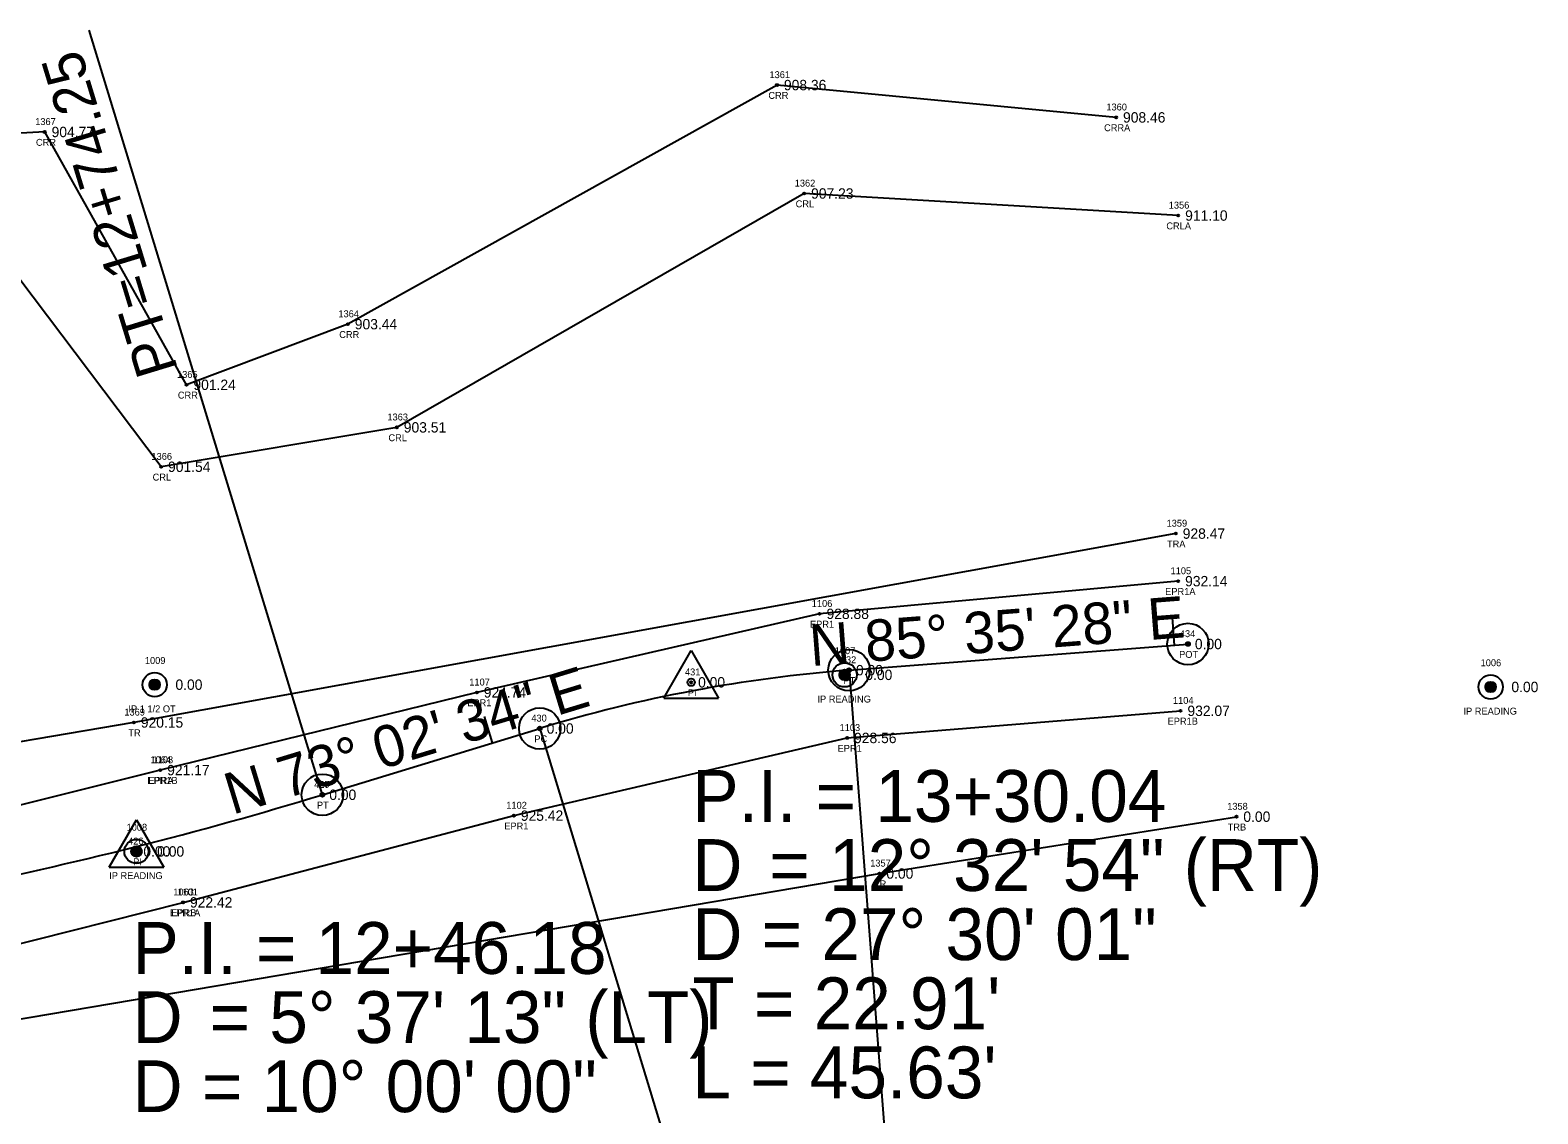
# Model space of a CAD drawing. Extents: x 1448136 to 1453623, y 1125056 to 1128842.
# Drawn here: x 1452130.2 to 1452348.3, y 1126988.8 to 1127145.6 of the extents above; entities that cross this region are included whole.
import ezdxf

# ---------------------------------------------------------------- set-up
doc = ezdxf.new("R2010")
doc.units = 0
for name, color, linetype in [('RD_EX_DV_Prop_txCode', 7, 'Continuous'), ('RD_EX_DV_PropPin', 7, 'Continuous'), ('RD_EX_H2O', 7, 'Continuous'), ('RD_EX_H2O_txCode', 7, 'Continuous'), ('RD_EX_Road', 7, 'Continuous'), ('RD_EX_Road_txCode', 7, 'Continuous'), ('RD_EX_TX_DV_Prop_ELEV', 7, 'Continuous'), ('RD_EX_TX_H2O_ELEV', 7, 'Continuous'), ('RD_EX_TX_Road_ELEV', 7, 'Continuous'), ('RD_EX_TX_VEG_ELEV', 7, 'Continuous'), ('RD_EX_VEG', 7, 'Continuous'), ('RD_EX_VEG_txCode', 7, 'Continuous'), ('RD_HC_Cl', 7, 'Continuous'), ('RD_HC_Data', 7, 'Continuous'), ('RD_HC_Data_Tic', 7, 'Continuous'), ('RD_HC_Survey_ELEV', 7, 'Continuous'), ('RD_HC_txCode', 7, 'Continuous'), ('RD_SMD_Locator', 7, 'Continuous')]:
    doc.layers.add(name, color=color, linetype=linetype)

msp = doc.modelspace()

# ---------------------------------------------------------------- linework, layer by layer
at = {"layer": 'RD_EX_DV_PropPin'}
for p, q in [((1452247.3, 1127052.08), (1452247.3, 1127052.47)), ((1452247.33, 1127051.98), (1452247.33, 1127052.57)), ((1452247.37, 1127051.91), (1452247.37, 1127052.64)), ((1452247.4, 1127051.85), (1452247.4, 1127052.7)), ((1452247.44, 1127051.8), (1452247.44, 1127052.75)), ((1452247.47, 1127051.76), (1452247.47, 1127052.79)), ((1452247.51, 1127051.72), (1452247.51, 1127052.83)), ((1452247.54, 1127051.69), (1452247.54, 1127052.86)), ((1452247.58, 1127051.66), (1452247.58, 1127052.88)), ((1452247.61, 1127051.64), (1452247.61, 1127052.91)), ((1452247.65, 1127051.62), (1452247.65, 1127052.93)), ((1452247.68, 1127051.6), (1452247.68, 1127052.95)), ((1452247.72, 1127051.58), (1452247.72, 1127052.97)), ((1452247.75, 1127051.57), (1452247.75, 1127052.98)), ((1452247.79, 1127051.55), (1452247.79, 1127053)), ((1452247.82, 1127051.54), (1452247.82, 1127053.01)), ((1452247.86, 1127051.53), (1452247.86, 1127053.02)), ((1452247.89, 1127051.53), (1452247.89, 1127053.02)), ((1452247.93, 1127051.52), (1452247.93, 1127053.03)), ((1452247.96, 1127051.52), (1452247.96, 1127053.03)), ((1452248, 1127051.51), (1452248, 1127053.03)), ((1452248.03, 1127051.51), (1452248.03, 1127053.04)), ((1452248.07, 1127051.51), (1452248.07, 1127053.03)), ((1452248.1, 1127051.52), (1452248.1, 1127053.03)), ((1452248.14, 1127051.52), (1452248.14, 1127053.03)), ((1452248.17, 1127051.53), (1452248.17, 1127053.02)), ((1452248.21, 1127051.53), (1452248.21, 1127053.02)), ((1452248.24, 1127051.54), (1452248.24, 1127053.01)), ((1452248.28, 1127051.55), (1452248.28, 1127053)), ((1452248.31, 1127051.57), (1452248.31, 1127052.98)), ((1452248.35, 1127051.58), (1452248.35, 1127052.97)), ((1452248.38, 1127051.6), (1452248.38, 1127052.95)), ((1452248.42, 1127051.62), (1452248.42, 1127052.93)), ((1452248.45, 1127051.64), (1452248.45, 1127052.91)), ((1452248.49, 1127051.66), (1452248.49, 1127052.88)), ((1452248.52, 1127051.69), (1452248.52, 1127052.86)), ((1452248.56, 1127051.72), (1452248.56, 1127052.83)), ((1452248.59, 1127051.76), (1452248.59, 1127052.79)), ((1452248.63, 1127051.8), (1452248.63, 1127052.75)), ((1452248.66, 1127051.85), (1452248.66, 1127052.7)), ((1452248.7, 1127051.91), (1452248.7, 1127052.64)), ((1452248.73, 1127051.98), (1452248.73, 1127052.57)), ((1452248.77, 1127052.08), (1452248.77, 1127052.47)), ((1452147.48, 1127050.65), (1452147.48, 1127051.04)), ((1452147.51, 1127050.55), (1452147.51, 1127051.14)), ((1452147.55, 1127050.48), (1452147.55, 1127051.21)), ((1452147.58, 1127050.42), (1452147.58, 1127051.27)), ((1452147.62, 1127050.37), (1452147.62, 1127051.32)), ((1452147.65, 1127050.33), (1452147.65, 1127051.36)), ((1452147.69, 1127050.29), (1452147.69, 1127051.4)), ((1452147.72, 1127050.26), (1452147.72, 1127051.43)), ((1452147.76, 1127050.24), (1452147.76, 1127051.46)), ((1452147.79, 1127050.21), (1452147.79, 1127051.48)), ((1452147.83, 1127050.19), (1452147.83, 1127051.5)), ((1452147.86, 1127050.17), (1452147.86, 1127051.52)), ((1452147.9, 1127050.15), (1452147.9, 1127051.54)), ((1452147.93, 1127050.14), (1452147.93, 1127051.55)), ((1452147.97, 1127050.12), (1452147.97, 1127051.57)), ((1452148, 1127050.11), (1452148, 1127051.58)), ((1452148.04, 1127050.1), (1452148.04, 1127051.59)), ((1452148.07, 1127050.1), (1452148.07, 1127051.59)), ((1452148.11, 1127050.09), (1452148.11, 1127051.6)), ((1452148.14, 1127050.09), (1452148.14, 1127051.6)), ((1452148.18, 1127050.09), (1452148.18, 1127051.61)), ((1452148.21, 1127050.08), (1452148.21, 1127051.61)), ((1452148.25, 1127050.09), (1452148.25, 1127051.61)), ((1452148.28, 1127050.09), (1452148.28, 1127051.6)), ((1452148.32, 1127050.09), (1452148.32, 1127051.6)), ((1452148.35, 1127050.1), (1452148.35, 1127051.59)), ((1452148.39, 1127050.1), (1452148.39, 1127051.59)), ((1452148.42, 1127050.11), (1452148.42, 1127051.58)), ((1452148.46, 1127050.12), (1452148.46, 1127051.57)), ((1452148.49, 1127050.14), (1452148.49, 1127051.55)), ((1452148.53, 1127050.15), (1452148.53, 1127051.54)), ((1452148.56, 1127050.17), (1452148.56, 1127051.52)), ((1452148.6, 1127050.19), (1452148.6, 1127051.5)), ((1452148.63, 1127050.21), (1452148.63, 1127051.48)), ((1452148.67, 1127050.24), (1452148.67, 1127051.46)), ((1452148.7, 1127050.26), (1452148.7, 1127051.43)), ((1452148.74, 1127050.29), (1452148.74, 1127051.4)), ((1452148.77, 1127050.33), (1452148.77, 1127051.36)), ((1452148.81, 1127050.37), (1452148.81, 1127051.32)), ((1452148.84, 1127050.42), (1452148.84, 1127051.27)), ((1452148.88, 1127050.48), (1452148.88, 1127051.21)), ((1452148.91, 1127050.55), (1452148.91, 1127051.14)), ((1452148.95, 1127050.65), (1452148.95, 1127051.04)), ((1452340.77, 1127050.33), (1452340.77, 1127050.72)), ((1452340.8, 1127050.22), (1452340.8, 1127050.82)), ((1452340.84, 1127050.15), (1452340.84, 1127050.89)), ((1452340.87, 1127050.1), (1452340.87, 1127050.95)), ((1452340.91, 1127050.05), (1452340.91, 1127051)), ((1452340.94, 1127050.01), (1452340.94, 1127051.04)), ((1452340.98, 1127049.97), (1452340.98, 1127051.07)), ((1452341.01, 1127049.94), (1452341.01, 1127051.1)), ((1452341.05, 1127049.91), (1452341.05, 1127051.13)), ((1452341.08, 1127049.89), (1452341.08, 1127051.16)), ((1452341.12, 1127049.87), (1452341.12, 1127051.18)), ((1452341.15, 1127049.85), (1452341.15, 1127051.2)), ((1452341.19, 1127049.83), (1452341.19, 1127051.22)), ((1452341.22, 1127049.82), (1452341.22, 1127051.23)), ((1452341.26, 1127049.8), (1452341.26, 1127051.24)), ((1452341.29, 1127049.79), (1452341.29, 1127051.25)), ((1452341.33, 1127049.78), (1452341.33, 1127051.26)), ((1452341.36, 1127049.77), (1452341.36, 1127051.27)), ((1452341.4, 1127049.77), (1452341.4, 1127051.28)), ((1452341.43, 1127049.77), (1452341.43, 1127051.28)), ((1452341.47, 1127049.76), (1452341.47, 1127051.28)), ((1452341.5, 1127049.76), (1452341.5, 1127051.28)), ((1452341.54, 1127049.76), (1452341.54, 1127051.28)), ((1452341.57, 1127049.77), (1452341.57, 1127051.28)), ((1452341.61, 1127049.77), (1452341.61, 1127051.28)), ((1452341.64, 1127049.77), (1452341.64, 1127051.27)), ((1452341.68, 1127049.78), (1452341.68, 1127051.26)), ((1452341.71, 1127049.79), (1452341.71, 1127051.25)), ((1452341.75, 1127049.8), (1452341.75, 1127051.24)), ((1452341.78, 1127049.82), (1452341.78, 1127051.23)), ((1452341.82, 1127049.83), (1452341.82, 1127051.22)), ((1452341.85, 1127049.85), (1452341.85, 1127051.2)), ((1452341.89, 1127049.87), (1452341.89, 1127051.18)), ((1452341.92, 1127049.89), (1452341.92, 1127051.16)), ((1452341.96, 1127049.91), (1452341.96, 1127051.13)), ((1452341.99, 1127049.94), (1452341.99, 1127051.1)), ((1452342.03, 1127049.97), (1452342.03, 1127051.07)), ((1452342.06, 1127050.01), (1452342.06, 1127051.04)), ((1452342.1, 1127050.05), (1452342.1, 1127051)), ((1452342.13, 1127050.1), (1452342.13, 1127050.95)), ((1452342.17, 1127050.15), (1452342.17, 1127050.89)), ((1452342.2, 1127050.22), (1452342.2, 1127050.82)), ((1452342.24, 1127050.33), (1452342.24, 1127050.72)), ((1452144.83, 1127026.52), (1452144.83, 1127026.91)), ((1452144.87, 1127026.42), (1452144.87, 1127027.02)), ((1452144.9, 1127026.35), (1452144.9, 1127027.09)), ((1452144.94, 1127026.29), (1452144.94, 1127027.15)), ((1452144.97, 1127026.24), (1452144.97, 1127027.19)), ((1452145.01, 1127026.2), (1452145.01, 1127027.23)), ((1452145.04, 1127026.17), (1452145.04, 1127027.27)), ((1452145.08, 1127026.14), (1452145.08, 1127027.3)), ((1452145.11, 1127026.11), (1452145.11, 1127027.33)), ((1452145.15, 1127026.08), (1452145.15, 1127027.35)), ((1452145.18, 1127026.06), (1452145.18, 1127027.37)), ((1452145.22, 1127026.04), (1452145.22, 1127027.39)), ((1452145.25, 1127026.03), (1452145.25, 1127027.41)), ((1452145.29, 1127026.01), (1452145.29, 1127027.43)), ((1452145.32, 1127026), (1452145.32, 1127027.44)), ((1452145.36, 1127025.99), (1452145.36, 1127027.45)), ((1452145.39, 1127025.98), (1452145.39, 1127027.46)), ((1452145.43, 1127025.97), (1452145.43, 1127027.47)), ((1452145.46, 1127025.96), (1452145.46, 1127027.47)), ((1452145.5, 1127025.96), (1452145.5, 1127027.48)), ((1452145.53, 1127025.96), (1452145.53, 1127027.48)), ((1452145.57, 1127025.96), (1452145.57, 1127027.48)), ((1452145.6, 1127025.96), (1452145.6, 1127027.48)), ((1452145.64, 1127025.96), (1452145.64, 1127027.48)), ((1452145.67, 1127025.96), (1452145.67, 1127027.47)), ((1452145.71, 1127025.97), (1452145.71, 1127027.47)), ((1452145.74, 1127025.98), (1452145.74, 1127027.46)), ((1452145.78, 1127025.99), (1452145.78, 1127027.45)), ((1452145.81, 1127026), (1452145.81, 1127027.44)), ((1452145.85, 1127026.01), (1452145.85, 1127027.43)), ((1452145.88, 1127026.03), (1452145.88, 1127027.41)), ((1452145.92, 1127026.04), (1452145.92, 1127027.39)), ((1452145.95, 1127026.06), (1452145.95, 1127027.37)), ((1452145.99, 1127026.08), (1452145.99, 1127027.35)), ((1452146.02, 1127026.11), (1452146.02, 1127027.33)), ((1452146.06, 1127026.14), (1452146.06, 1127027.3)), ((1452146.09, 1127026.17), (1452146.09, 1127027.27)), ((1452146.13, 1127026.2), (1452146.13, 1127027.23)), ((1452146.16, 1127026.24), (1452146.16, 1127027.19)), ((1452146.2, 1127026.29), (1452146.2, 1127027.15)), ((1452146.23, 1127026.35), (1452146.23, 1127027.09)), ((1452146.27, 1127026.42), (1452146.27, 1127027.02)), ((1452146.3, 1127026.52), (1452146.3, 1127026.91))]:
    msp.add_line(p, q, dxfattribs=at)
for centre, radius in [((1452148.21, 1127050.85), 1.75), ((1452248.03, 1127052.27), 1.75), ((1452248.03, 1127052.27), 0.761), ((1452341.5, 1127050.52), 1.75), ((1452148.21, 1127050.85), 0.761), ((1452341.5, 1127050.52), 0.761), ((1452145.57, 1127026.72), 1.75), ((1452145.57, 1127026.72), 0.761)]:
    msp.add_circle(centre, radius, dxfattribs=at)
at = {"layer": 'RD_EX_H2O'}
for points in [[(1452287.31, 1127132.93), (1452238.25, 1127137.61), (1452176.16, 1127103.01), (1452152.81, 1127094.24), (1452132.29, 1127130.82), (1452091.98, 1127128.64)], [(1452296.3, 1127118.73), (1452242.18, 1127121.92), (1452183.25, 1127088.08), (1452149.14, 1127082.38), (1452122.3, 1127117.91), (1452087.28, 1127110.29)]]:
    msp.add_lwpolyline(points, dxfattribs=at)
at = {"layer": 'RD_EX_Road'}
for points in [[(1452296.29, 1127065.83), (1452244.41, 1127061.1), (1452194.82, 1127049.73), (1452149.01, 1127038.49)], [(1452152.31, 1127019.35), (1452200.18, 1127031.9), (1452248.4, 1127043.14), (1452296.63, 1127047.07)], [(1452149.01, 1127038.49), (1452106.48, 1127027.85), (1452082.46, 1127021.08), (1452045.59, 1127011.82), (1452002.97, 1126996.13), (1451959.33, 1126960.73), (1451946.24, 1126940.07), (1451939.81, 1126935.13), (1451933.14, 1126934.05), (1451919.64, 1126943.05), (1451878.71, 1126971.14)], [(1452328.31, 1126661.73), (1452287.09, 1126689.84), (1452246.03, 1126718.01), (1452205.32, 1126746.34), (1452164.06, 1126774.06), (1452123.37, 1126802.45), (1452082.65, 1126830.42), (1452041.69, 1126858.52), (1452001.17, 1126886.81), (1451960.88, 1126914.87), (1451958.61, 1126919.72), (1451960.49, 1126923.88), (1451963.74, 1126930.05), (1451974.47, 1126951.2), (1452008.52, 1126983.3), (1452048.25, 1126993.66), (1452104.12, 1127007.18), (1452152.31, 1127019.35)]]:
    msp.add_lwpolyline(points, dxfattribs=at)
at = {"layer": 'RD_EX_VEG'}
for points in [[(1452295.95, 1127072.71), (1452145.2, 1127045.38), (1452114.53, 1127040.15), (1452064.57, 1127077.19)], [(1452345.62, 1126685.22), (1452295.11, 1126702.27), (1452093.42, 1126839.73), (1451967.4, 1126923.31), (1452009.8, 1126977.57), (1452079.04, 1126994.05), (1452253.07, 1127023.53), (1452304.72, 1127031.75)]]:
    msp.add_lwpolyline(points, dxfattribs=at)
at = {"layer": 'RD_HC_Cl'}
for p, q in [((1452248.67, 1127052.95), (1452297.71, 1127056.73)), ((1452172.47, 1127034.92), (1452203.92, 1127044.51))]:
    msp.add_line(p, q, dxfattribs=at)
for centre, radius, start, end in [((1452264.68, 1126845.22), 208.35, 94.4089, 106.9571), ((1452005.37, 1127582.96), 572.95, 281.3368, 286.9571)]:
    msp.add_arc(centre, radius, start, end, dxfattribs=at)
at = {"layer": 'RD_HC_Data'}
for p, q in [((1452172.47, 1127034.92), (1452138.74, 1127145.55)), ((1452221.86, 1127048.9), (1452225.83, 1127055.78)), ((1452225.83, 1127055.78), (1452229.8, 1127048.9)), ((1452248.67, 1127052.95), (1452257.58, 1126937.34)), ((1452221.86, 1127048.9), (1452229.8, 1127048.9)), ((1452203.92, 1127044.51), (1452237.88, 1126933.13)), ((1452141.6, 1127024.43), (1452145.57, 1127031.31)), ((1452145.57, 1127031.31), (1452149.54, 1127024.43)), ((1452141.6, 1127024.43), (1452149.54, 1127024.43))]:
    msp.add_line(p, q, dxfattribs=at)
for centre, radius in [((1452297.71, 1127056.73), 3), ((1452297.71, 1127056.73), 0.282), ((1452248.67, 1127052.95), 3), ((1452248.67, 1127052.95), 0.282), ((1452225.83, 1127051.19), 0.529), ((1452203.92, 1127044.51), 3), ((1452203.92, 1127044.51), 0.282), ((1452172.47, 1127034.92), 3), ((1452172.47, 1127034.92), 3), ((1452172.47, 1127034.92), 0.282), ((1452172.47, 1127034.92), 0.282), ((1452145.57, 1127026.72), 0.529)]:
    msp.add_circle(centre, radius, dxfattribs=at)
at = {"layer": 'RD_HC_Data_Tic'}
for p, q in [((1452295.77, 1127056.58), (1452295.46, 1127060.57)), ((1452197.1, 1127042.43), (1452195.93, 1127046.26))]:
    msp.add_line(p, q, dxfattribs=at)
at = {"layer": 'RD_SMD_Locator'}
for centre in [(1452238.25, 1127137.61), (1452287.31, 1127132.93), (1452132.29, 1127130.82), (1452242.18, 1127121.92), (1452296.3, 1127118.73), (1452176.16, 1127103.01), (1452152.81, 1127094.24), (1452183.25, 1127088.08), (1452149.14, 1127082.38), (1452295.95, 1127072.71), (1452296.29, 1127065.83), (1452244.41, 1127061.1), (1452297.71, 1127056.73), (1452248.03, 1127052.27), (1452248.67, 1127052.95), (1452148.21, 1127050.85), (1452194.82, 1127049.73), (1452225.83, 1127051.19), (1452341.5, 1127050.52), (1452145.2, 1127045.38), (1452296.63, 1127047.07), (1452203.92, 1127044.51), (1452248.4, 1127043.14), (1452149.01, 1127038.49), (1452149.01, 1127038.49), (1452172.47, 1127034.92), (1452172.47, 1127034.92), (1452200.18, 1127031.9), (1452304.72, 1127031.75), (1452145.57, 1127026.72), (1452145.57, 1127026.72), (1452253.07, 1127023.53), (1452152.31, 1127019.35), (1452152.31, 1127019.35)]:
    msp.add_circle(centre, 0.15, dxfattribs=at)

# ---------------------------------------------------------------- texts
at = {"layer": 'RD_EX_DV_Prop_txCode'}
for s, p in [('1009', (1452146.79, 1127053.85)), ('1007', (1452246.61, 1127055.27)), ('1006', (1452340.05, 1127053.52)), ('IP 1 1/2 OT', (1452144.41, 1127046.85)), ('IP READING', (1452244.1, 1127048.27)), ('IP READING', (1452337.57, 1127046.52)), ('1008', (1452144.14, 1127029.72)), ('IP READING', (1452141.63, 1127022.72))]:
    msp.add_text(s, height=1, dxfattribs=at).set_placement(p)
at = {"layer": 'RD_EX_H2O_txCode'}
for s, p in [('1361', (1452237.16, 1127138.61)), ('CRR', (1452237, 1127135.61)), ('1360', (1452285.9, 1127133.93)), ('1367', (1452130.92, 1127131.82)), ('CRRA', (1452285.57, 1127130.93)), ('CRR', (1452131.03, 1127128.82)), ('1362', (1452240.81, 1127122.92)), ('CRL', (1452240.95, 1127119.92)), ('1356', (1452294.93, 1127119.73)), ('CRLA', (1452294.58, 1127116.73)), ('1364', (1452174.79, 1127104.01)), ('CRR', (1452174.91, 1127101.01)), ('1365', (1452151.44, 1127095.24)), ('CRR', (1452151.56, 1127092.24)), ('1363', (1452181.88, 1127089.08)), ('CRL', (1452182.03, 1127086.08)), ('1366', (1452147.74, 1127083.38)), ('CRL', (1452147.91, 1127080.38))]:
    msp.add_text(s, height=1, dxfattribs=at).set_placement(p)
at = {"layer": 'RD_EX_Road_txCode'}
for s, p in [('1105', (1452295.19, 1127066.83)), ('1106', (1452243.28, 1127062.1)), ('EPR1A', (1452294.41, 1127063.83)), ('EPR1', (1452243.02, 1127059.1)), ('1107', (1452193.72, 1127050.73)), ('EPR1', (1452193.43, 1127047.73)), ('1104', (1452295.53, 1127048.07)), ('EPR1B', (1452294.76, 1127045.07)), ('1103', (1452247.3, 1127044.14)), ('EPR1', (1452247.01, 1127041.14)), ('1064', (1452147.6, 1127039.49)), ('1108', (1452147.9, 1127039.49)), ('EPR1B', (1452147.14, 1127036.49)), ('EPRA', (1452147.29, 1127036.49)), ('1102', (1452199.08, 1127032.9)), ('EPR1', (1452198.79, 1127029.9)), ('1063', (1452150.9, 1127020.35)), ('1101', (1452151.49, 1127020.35)), ('EPR1A', (1452150.42, 1127017.35)), ('EPRB', (1452150.6, 1127017.35))]:
    msp.add_text(s, height=1, dxfattribs=at).set_placement(p)
at = {"layer": 'RD_EX_TX_DV_Prop_ELEV'}
for p in [(1452251.03, 1127051.52), (1452151.21, 1127050.1), (1452344.5, 1127049.77), (1452148.57, 1127025.97)]:
    msp.add_text('0.00', height=1.5, dxfattribs=at).set_placement(p)
at = {"layer": 'RD_EX_TX_H2O_ELEV'}
for s, p in [('908.36', (1452239.25, 1127136.86)), ('908.46', (1452288.31, 1127132.18)), ('904.77', (1452133.29, 1127130.07)), ('907.23', (1452243.18, 1127121.17)), ('911.10', (1452297.3, 1127117.98)), ('903.44', (1452177.16, 1127102.26)), ('901.24', (1452153.81, 1127093.49)), ('903.51', (1452184.25, 1127087.33)), ('901.54', (1452150.14, 1127081.63))]:
    msp.add_text(s, height=1.5, dxfattribs=at).set_placement(p)
at = {"layer": 'RD_EX_TX_Road_ELEV'}
for s, p in [('932.14', (1452297.29, 1127065.08)), ('928.88', (1452245.41, 1127060.35)), ('924.74', (1452195.82, 1127048.98)), ('932.07', (1452297.63, 1127046.32)), ('928.56', (1452249.4, 1127042.39)), ('921.17', (1452150.01, 1127037.74)), ('921.17', (1452150.01, 1127037.74)), ('925.42', (1452201.18, 1127031.15)), ('922.42', (1452153.31, 1127018.6)), ('922.42', (1452153.31, 1127018.6))]:
    msp.add_text(s, height=1.5, dxfattribs=at).set_placement(p)
at = {"layer": 'RD_EX_TX_VEG_ELEV'}
for s, p in [('928.47', (1452296.95, 1127071.96)), ('920.15', (1452146.2, 1127044.63)), ('0.00', (1452305.72, 1127031)), ('0.00', (1452254.07, 1127022.78))]:
    msp.add_text(s, height=1.5, dxfattribs=at).set_placement(p)
at = {"layer": 'RD_EX_VEG_txCode'}
for s, p in [('1359', (1452294.61, 1127073.71)), ('TRA', (1452294.67, 1127070.71)), ('1369', (1452143.82, 1127046.38)), ('TR', (1452144.4, 1127043.38)), ('1358', (1452303.38, 1127032.75)), ('TRB', (1452303.45, 1127029.75)), ('1357', (1452251.73, 1127024.53)), ('TR', (1452252.28, 1127021.53))]:
    msp.add_text(s, height=1, dxfattribs=at).set_placement(p)
at = {"layer": 'RD_HC_Data'}
for s, rotation, p in [('PT=12+74.25', 106.9571, (1452151.6, 1127096.51)), ('N 85%%d 35\' 28" E', 4.4089, (1452243.18, 1127053.53)), ('N 73%%d 02\' 34" E', 16.9571, (1452159.45, 1127032))]:
    msp.add_text(s, height=6, rotation=rotation, dxfattribs=at).set_placement(p)
for s, p in [('P.I. = 13+30.04', (1452226, 1127031)), ('D', (1452226, 1127021)), ('    = 12%%d 32\' 54" (RT)', (1452226, 1127021)), ('D = 27%%d 30\' 01"', (1452226, 1127011)), ('P.I. = 12+46.18', (1452145, 1127009)), ("T = 22.91'", (1452226, 1127001)), ('D', (1452145, 1126999)), ('    = 5%%d 37\' 13" (LT)', (1452145, 1126999)), ("L = 45.63'", (1452226, 1126991)), ('D = 10%%d 00\' 00"', (1452145, 1126989))]:
    msp.add_text(s, height=7.5, dxfattribs=at).set_placement(p)
at = {"layer": 'RD_HC_Survey_ELEV'}
for p in [(1452298.71, 1127055.98), (1452249.67, 1127052.2), (1452226.83, 1127050.44), (1452204.92, 1127043.76), (1452173.47, 1127034.17), (1452173.47, 1127034.17), (1452146.57, 1127025.97)]:
    msp.add_text('0.00', height=1.5, dxfattribs=at).set_placement(p)
at = {"layer": 'RD_HC_txCode'}
for s, p in [('434', (1452296.53, 1127057.73)), ('432', (1452247.48, 1127053.95)), ('POT', (1452296.43, 1127054.73)), ('431', (1452224.93, 1127052.19)), ('PI', (1452225.35, 1127049.19)), ('PT', (1452247.87, 1127050.95)), ('430', (1452202.7, 1127045.51)), ('PC', (1452203.14, 1127042.51)), ('427', (1452171.29, 1127035.92)), ('429', (1452171.29, 1127035.92)), ('PT', (1452171.68, 1127032.92)), ('PT', (1452171.68, 1127032.92)), ('426', (1452144.36, 1127027.72)), ('PI', (1452145.1, 1127024.72))]:
    msp.add_text(s, height=1, dxfattribs=at).set_placement(p)

doc.saveas('drawing.dxf')
